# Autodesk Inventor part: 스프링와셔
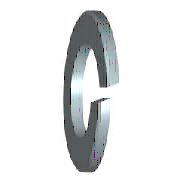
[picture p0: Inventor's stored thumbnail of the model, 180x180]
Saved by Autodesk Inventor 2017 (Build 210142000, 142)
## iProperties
Created: 2012-02
Part Number: 스프링와셔
Material: 강철, 연강
Description: 스프링 와셔
Document SubType Name: Modeling
Standard: JIS B 1251
Designer: mduedu
Standards Organization: JIS
Language: ko-KR
Size Designation: 번호 2 4
Categories: <MemberInstance><Categories><Category DisplayName="조임쇠" InternalName="e4da775c-781d-43d5-af7c-5136215cf5a6" Mnemonic="FSTN"><Category DisplayName="와셔" InternalN
Density: 7.85 g/cm^3
Mass: 0.246957 g
Surface Area: 1.02615 cm^2
Volume: 0.0314594 cm^3
Appearance: 파란색 - 벽 페인트 - 광택
IsCustomPart: 1
Author: mduedu
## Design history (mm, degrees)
sketch "스케치1"
  geometry: C1 r 3.8 at (0, 0); C2 r 2.05 at (0, 0); 1 further point
  constraints: 2 centre point, 2 coincident
  dimensions: "d0" = 4.1 diameter of C2 (= SD1); "d1" = 7.6 diameter of C1 (= SD2)
extrude "본체" new body sketch "스케치1" distance "d2" = 1 (= SD); taper "d3" = 0 deg
sketch "스케치2"
  geometry: L1 (0, -2.05)-(0, 2.05) reference; L2 (1, 3.8)-(1, -3.8) reference; L3 (-1.2, 0)-(7.2, 0) reference; L4 (0, -0.2)-(1, 0.164); L5 (0, 0.2)-(1, 0.564)
  constraints: 4 end point, 4 point on line, 1 parallel
  dimensions: "d4" = 0.2 distance from line of L3 L4.start (= 0.2 x SD); "d5" = 0.2 distance from line of L3 L5.start (= 0.2 x SD); "d6" = 70 deg angle of L2 L4 (= FAWI)
extrude "절단부" cut sketch "스케치2" stored distance "d7" = 1 (= SD); taper "d8" = 0 deg
workaxis "Work Axis1"
workplane "Work Plane1"
body "Solid1"
other parameters: "SD1" = 4.1 [user parameter; used in 1 equation term], "SD2" = 7.6 [user parameter; used in 1 equation term], "SD" = 1 [user parameter; used in 4 equation terms], "FAWI" = 70 deg [user parameter; used in 1 equation term], "d9" = 0, "d10" = 0, "d11" = 0, "d12" = 0, "SDI" = 1.4 [user parameter], "NND" = 4 [user parameter]
